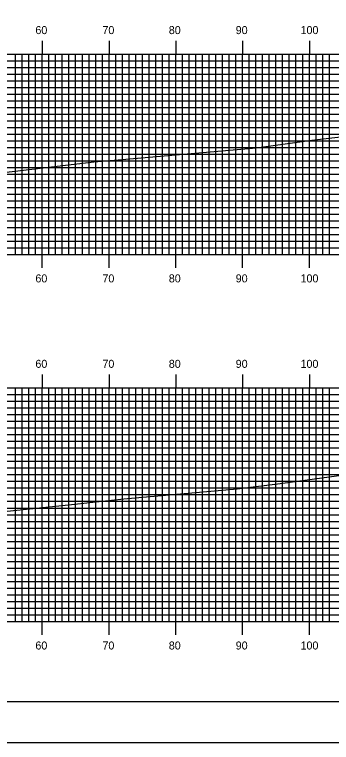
# Model space of a CAD drawing. Extents: x 1818850 to 1819194, y 442591 to 442811.
# Drawn here: x 1819072 to 1819119.5, y 442590.5 to 442699.6 of the extents above; entities that cross this region are included whole.
import ezdxf

# ---------------------------------------------------------------- set-up
doc = ezdxf.new("R2010")
doc.units = 0
for name, color, linetype in [('BORDER', 7, 'Continuous'), ('H_V ANNOTATION', 7, 'Continuous'), ('MAJOR', 7, 'Continuous'), ('MINOR', 7, 'Continuous'), ('PLOT BOUNDARY', 7, 'Continuous'), ('S_Roadway_Centerline', 7, 'Continuous')]:
    doc.layers.add(name, color=color, linetype=linetype)

msp = doc.modelspace()

# ---------------------------------------------------------------- linework, layer by layer
at = {"layer": 'BORDER'}
msp.add_lwpolyline([(1818866.55, 442596.67), (1819186.55, 442596.67), (1819186.55, 442806.67), (1818866.55, 442806.67)], close=True, dxfattribs=at)
at = {"layer": 'MAJOR'}
for p, q in [((1819076.15, 442695.67), (1819076.15, 442693.67)), ((1819086.15, 442695.67), (1819086.15, 442693.67)), ((1819096.15, 442695.67), (1819096.15, 442693.67)), ((1819106.15, 442695.67), (1819106.15, 442693.67)), ((1819116.15, 442695.67), (1819116.15, 442693.67)), ((1818876.15, 442693.67), (1819156.15, 442693.67)), ((1818876.15, 442693.67), (1819156.15, 442693.67)), ((1819076.15, 442663.67), (1819076.15, 442693.67)), ((1819086.15, 442663.67), (1819086.15, 442693.67)), ((1819096.15, 442663.67), (1819096.15, 442693.67)), ((1819106.15, 442663.67), (1819106.15, 442693.67)), ((1819116.15, 442663.67), (1819116.15, 442693.67)), ((1818876.15, 442688.67), (1819156.15, 442688.67)), ((1818876.15, 442683.67), (1819156.15, 442683.67)), ((1818876.15, 442678.67), (1819156.15, 442678.67)), ((1818876.15, 442673.67), (1819156.15, 442673.67)), ((1818876.15, 442668.67), (1819156.15, 442668.67)), ((1818876.15, 442663.67), (1819156.15, 442663.67)), ((1818876.15, 442663.67), (1819156.15, 442663.67)), ((1819076.15, 442661.66), (1819076.15, 442663.67)), ((1819086.15, 442661.66), (1819086.15, 442663.67)), ((1819096.15, 442661.66), (1819096.15, 442663.67)), ((1819106.15, 442661.66), (1819106.15, 442663.67)), ((1819116.15, 442661.66), (1819116.15, 442663.67)), ((1819076.15, 442645.67), (1819076.15, 442643.67)), ((1819086.15, 442645.67), (1819086.15, 442643.67)), ((1819096.15, 442645.67), (1819096.15, 442643.67)), ((1819106.15, 442645.67), (1819106.15, 442643.67)), ((1819116.15, 442645.67), (1819116.15, 442643.67)), ((1818876.15, 442643.67), (1819156.15, 442643.67)), ((1818876.15, 442643.67), (1819156.15, 442643.67)), ((1819076.15, 442608.67), (1819076.15, 442643.67)), ((1819086.15, 442608.67), (1819086.15, 442643.67)), ((1819096.15, 442608.67), (1819096.15, 442643.67)), ((1819106.15, 442608.67), (1819106.15, 442643.67)), ((1819116.15, 442608.67), (1819116.15, 442643.67)), ((1818876.15, 442638.67), (1819156.15, 442638.67)), ((1818876.15, 442633.67), (1819156.15, 442633.67)), ((1818876.15, 442628.67), (1819156.15, 442628.67)), ((1818876.15, 442623.67), (1819156.15, 442623.67)), ((1818876.15, 442618.67), (1819156.15, 442618.67)), ((1818876.15, 442613.67), (1819156.15, 442613.67)), ((1818876.15, 442608.67), (1819156.15, 442608.67)), ((1818876.15, 442608.67), (1819156.15, 442608.67)), ((1819076.15, 442606.66), (1819076.15, 442608.67)), ((1819086.15, 442606.66), (1819086.15, 442608.67)), ((1819096.15, 442606.66), (1819096.15, 442608.67)), ((1819106.15, 442606.66), (1819106.15, 442608.67)), ((1819116.15, 442606.66), (1819116.15, 442608.67))]:
    msp.add_line(p, q, dxfattribs=at)
at = {"layer": 'MINOR'}
for p, q in [((1819072.15, 442663.67), (1819072.15, 442693.67)), ((1819073.15, 442663.67), (1819073.15, 442693.67)), ((1819074.15, 442663.67), (1819074.15, 442693.67)), ((1819075.15, 442663.67), (1819075.15, 442693.67)), ((1819077.15, 442663.67), (1819077.15, 442693.67)), ((1819078.15, 442663.67), (1819078.15, 442693.67)), ((1819079.15, 442663.67), (1819079.15, 442693.67)), ((1819080.15, 442663.67), (1819080.15, 442693.67)), ((1819081.15, 442663.67), (1819081.15, 442693.67)), ((1819082.15, 442663.67), (1819082.15, 442693.67)), ((1819083.15, 442663.67), (1819083.15, 442693.67)), ((1819084.15, 442663.67), (1819084.15, 442693.67)), ((1819085.15, 442663.67), (1819085.15, 442693.67)), ((1819087.15, 442663.67), (1819087.15, 442693.67)), ((1819088.15, 442663.67), (1819088.15, 442693.67)), ((1819089.15, 442663.67), (1819089.15, 442693.67)), ((1819090.15, 442663.67), (1819090.15, 442693.67)), ((1819091.15, 442663.67), (1819091.15, 442693.67)), ((1819092.15, 442663.67), (1819092.15, 442693.67)), ((1819093.15, 442663.67), (1819093.15, 442693.67)), ((1819094.15, 442663.67), (1819094.15, 442693.67)), ((1819095.15, 442663.67), (1819095.15, 442693.67)), ((1819097.15, 442663.67), (1819097.15, 442693.67)), ((1819098.15, 442663.67), (1819098.15, 442693.67)), ((1819099.15, 442663.67), (1819099.15, 442693.67)), ((1819100.15, 442663.67), (1819100.15, 442693.67)), ((1819101.15, 442663.67), (1819101.15, 442693.67)), ((1819102.15, 442663.67), (1819102.15, 442693.67)), ((1819103.15, 442663.67), (1819103.15, 442693.67)), ((1819104.15, 442663.67), (1819104.15, 442693.67)), ((1819105.15, 442663.67), (1819105.15, 442693.67)), ((1819107.15, 442663.67), (1819107.15, 442693.67)), ((1819108.15, 442663.67), (1819108.15, 442693.67)), ((1819109.15, 442663.67), (1819109.15, 442693.67)), ((1819110.15, 442663.67), (1819110.15, 442693.67)), ((1819111.15, 442663.67), (1819111.15, 442693.67)), ((1819112.15, 442663.67), (1819112.15, 442693.67)), ((1819113.15, 442663.67), (1819113.15, 442693.67)), ((1819114.15, 442663.67), (1819114.15, 442693.67)), ((1819115.15, 442663.67), (1819115.15, 442693.67)), ((1819117.15, 442663.67), (1819117.15, 442693.67)), ((1819118.15, 442663.67), (1819118.15, 442693.67)), ((1819119.15, 442663.67), (1819119.15, 442693.67)), ((1818876.15, 442692.67), (1819156.15, 442692.67)), ((1818876.15, 442691.67), (1819156.15, 442691.67)), ((1818876.15, 442690.67), (1819156.15, 442690.67)), ((1818876.15, 442689.67), (1819156.15, 442689.67)), ((1818876.15, 442687.67), (1819156.15, 442687.67)), ((1818876.15, 442686.67), (1819156.15, 442686.67)), ((1818876.15, 442685.67), (1819156.15, 442685.67)), ((1818876.15, 442684.67), (1819156.15, 442684.67)), ((1818876.15, 442682.67), (1819156.15, 442682.67)), ((1818876.15, 442681.67), (1819156.15, 442681.67)), ((1818876.15, 442680.67), (1819156.15, 442680.67)), ((1818876.15, 442679.67), (1819156.15, 442679.67)), ((1818876.15, 442677.67), (1819156.15, 442677.67)), ((1818876.15, 442676.67), (1819156.15, 442676.67)), ((1818876.15, 442675.67), (1819156.15, 442675.67)), ((1818876.15, 442674.67), (1819156.15, 442674.67)), ((1818876.15, 442672.67), (1819156.15, 442672.67)), ((1818876.15, 442671.67), (1819156.15, 442671.67)), ((1818876.15, 442670.67), (1819156.15, 442670.67)), ((1818876.15, 442669.67), (1819156.15, 442669.67)), ((1818876.15, 442667.67), (1819156.15, 442667.67)), ((1818876.15, 442666.67), (1819156.15, 442666.67)), ((1818876.15, 442665.67), (1819156.15, 442665.67)), ((1818876.15, 442664.67), (1819156.15, 442664.67)), ((1819072.15, 442608.67), (1819072.15, 442643.67)), ((1819073.15, 442608.67), (1819073.15, 442643.67)), ((1819074.15, 442608.67), (1819074.15, 442643.67)), ((1819075.15, 442608.67), (1819075.15, 442643.67)), ((1819077.15, 442608.67), (1819077.15, 442643.67)), ((1819078.15, 442608.67), (1819078.15, 442643.67)), ((1819079.15, 442608.67), (1819079.15, 442643.67)), ((1819080.15, 442608.67), (1819080.15, 442643.67)), ((1819081.15, 442608.67), (1819081.15, 442643.67)), ((1819082.15, 442608.67), (1819082.15, 442643.67)), ((1819083.15, 442608.67), (1819083.15, 442643.67)), ((1819084.15, 442608.67), (1819084.15, 442643.67)), ((1819085.15, 442608.67), (1819085.15, 442643.67)), ((1819087.15, 442608.67), (1819087.15, 442643.67)), ((1819088.15, 442608.67), (1819088.15, 442643.67)), ((1819089.15, 442608.67), (1819089.15, 442643.67)), ((1819090.15, 442608.67), (1819090.15, 442643.67)), ((1819091.15, 442608.67), (1819091.15, 442643.67)), ((1819092.15, 442608.67), (1819092.15, 442643.67)), ((1819093.15, 442608.67), (1819093.15, 442643.67)), ((1819094.15, 442608.67), (1819094.15, 442643.67)), ((1819095.15, 442608.67), (1819095.15, 442643.67)), ((1819097.15, 442608.67), (1819097.15, 442643.67)), ((1819098.15, 442608.67), (1819098.15, 442643.67)), ((1819099.15, 442608.67), (1819099.15, 442643.67)), ((1819100.15, 442608.67), (1819100.15, 442643.67)), ((1819101.15, 442608.67), (1819101.15, 442643.67)), ((1819102.15, 442608.67), (1819102.15, 442643.67)), ((1819103.15, 442608.67), (1819103.15, 442643.67)), ((1819104.15, 442608.67), (1819104.15, 442643.67)), ((1819105.15, 442608.67), (1819105.15, 442643.67)), ((1819107.15, 442608.67), (1819107.15, 442643.67)), ((1819108.15, 442608.67), (1819108.15, 442643.67)), ((1819109.15, 442608.67), (1819109.15, 442643.67)), ((1819110.15, 442608.67), (1819110.15, 442643.67)), ((1819111.15, 442608.67), (1819111.15, 442643.67)), ((1819112.15, 442608.67), (1819112.15, 442643.67)), ((1819113.15, 442608.67), (1819113.15, 442643.67)), ((1819114.15, 442608.67), (1819114.15, 442643.67)), ((1819115.15, 442608.67), (1819115.15, 442643.67)), ((1819117.15, 442608.67), (1819117.15, 442643.67)), ((1819118.15, 442608.67), (1819118.15, 442643.67)), ((1819119.15, 442608.67), (1819119.15, 442643.67)), ((1818876.15, 442642.67), (1819156.15, 442642.67)), ((1818876.15, 442641.67), (1819156.15, 442641.67)), ((1818876.15, 442640.67), (1819156.15, 442640.67)), ((1818876.15, 442639.67), (1819156.15, 442639.67)), ((1818876.15, 442637.67), (1819156.15, 442637.67)), ((1818876.15, 442636.67), (1819156.15, 442636.67)), ((1818876.15, 442635.67), (1819156.15, 442635.67)), ((1818876.15, 442634.67), (1819156.15, 442634.67)), ((1818876.15, 442632.67), (1819156.15, 442632.67)), ((1818876.15, 442631.67), (1819156.15, 442631.67)), ((1818876.15, 442630.67), (1819156.15, 442630.67)), ((1818876.15, 442629.67), (1819156.15, 442629.67)), ((1818876.15, 442627.67), (1819156.15, 442627.67)), ((1818876.15, 442626.67), (1819156.15, 442626.67)), ((1818876.15, 442625.67), (1819156.15, 442625.67)), ((1818876.15, 442624.67), (1819156.15, 442624.67)), ((1818876.15, 442622.67), (1819156.15, 442622.67)), ((1818876.15, 442621.67), (1819156.15, 442621.67)), ((1818876.15, 442620.67), (1819156.15, 442620.67)), ((1818876.15, 442619.67), (1819156.15, 442619.67)), ((1818876.15, 442617.67), (1819156.15, 442617.67)), ((1818876.15, 442616.67), (1819156.15, 442616.67)), ((1818876.15, 442615.67), (1819156.15, 442615.67)), ((1818876.15, 442614.67), (1819156.15, 442614.67)), ((1818876.15, 442612.67), (1819156.15, 442612.67)), ((1818876.15, 442611.67), (1819156.15, 442611.67)), ((1818876.15, 442610.67), (1819156.15, 442610.67)), ((1818876.15, 442609.67), (1819156.15, 442609.67))]:
    msp.add_line(p, q, dxfattribs=at)
at = {"layer": 'PLOT BOUNDARY'}
msp.add_lwpolyline([(1818850.36, 442590.55), (1819190.36, 442590.55), (1819190.36, 442810.55), (1818850.36, 442810.55)], close=True, dxfattribs=at)
at = {"layer": 'S_Roadway_Centerline'}
for points in [[(1819070.78, 442675.98), (1819083.88, 442677.52), (1819088.1, 442677.88), (1819108.17, 442679.61), (1819116.53, 442680.76), (1819131.59, 442682.54), (1819132.8, 442682.68), (1819133.55, 442682.76), (1819136.43, 442683.09), (1819156.15, 442685.18)], [(1819064.07, 442624.48), (1819079.13, 442626.05), (1819088.35, 442627.04), (1819105.32, 442628.54), (1819112.2, 442629.38), (1819126.08, 442631.29), (1819129.29, 442631.7), (1819137.42, 442632.57), (1819156.15, 442634.19)]]:
    msp.add_lwpolyline(points, dxfattribs=at)

# ---------------------------------------------------------------- texts
at = {"layer": 'H_V ANNOTATION'}
for s, p in [('60', (1819075.12, 442696.67)), ('70', (1819085.16, 442696.67)), ('80', (1819095.1, 442696.67)), ('90', (1819105.12, 442696.67)), ('100', (1819114.83, 442696.67)), ('60', (1819075.12, 442659.47)), ('70', (1819085.16, 442659.47)), ('80', (1819095.1, 442659.47)), ('90', (1819105.12, 442659.47)), ('100', (1819114.83, 442659.47)), ('60', (1819075.12, 442646.67)), ('70', (1819085.16, 442646.67)), ('80', (1819095.1, 442646.67)), ('90', (1819105.12, 442646.67)), ('100', (1819114.83, 442646.67)), ('60', (1819075.12, 442604.47)), ('70', (1819085.16, 442604.47)), ('80', (1819095.1, 442604.47)), ('90', (1819105.12, 442604.47)), ('100', (1819114.83, 442604.47))]:
    msp.add_text(s, height=1.2, dxfattribs=at).set_placement(p)

doc.saveas('drawing.dxf')
